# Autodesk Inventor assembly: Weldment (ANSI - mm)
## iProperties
Length Units: 11269
Angle Units: 11283
Time Units: 11279
Mass Units: 11290
Length Display Precision: 3
Angle Display Precision: 2
Part Number: Weldment (ANSI - mm)
Document SubType Name: Weldment
Created: 2002-06
Designer: smithga
Part Number: Assembly2
Created: 2003-01
Designer: Owner
Control State: 0
Master: False
Shininess: 64.0
Angle Units: 11279
Time Units: 11290
Mass Units: 11283
Compacted: True
Density: 0.0
Volumn: 0.0
Area: 0.0
PropertySet Name: Model Information
Author: Owner
